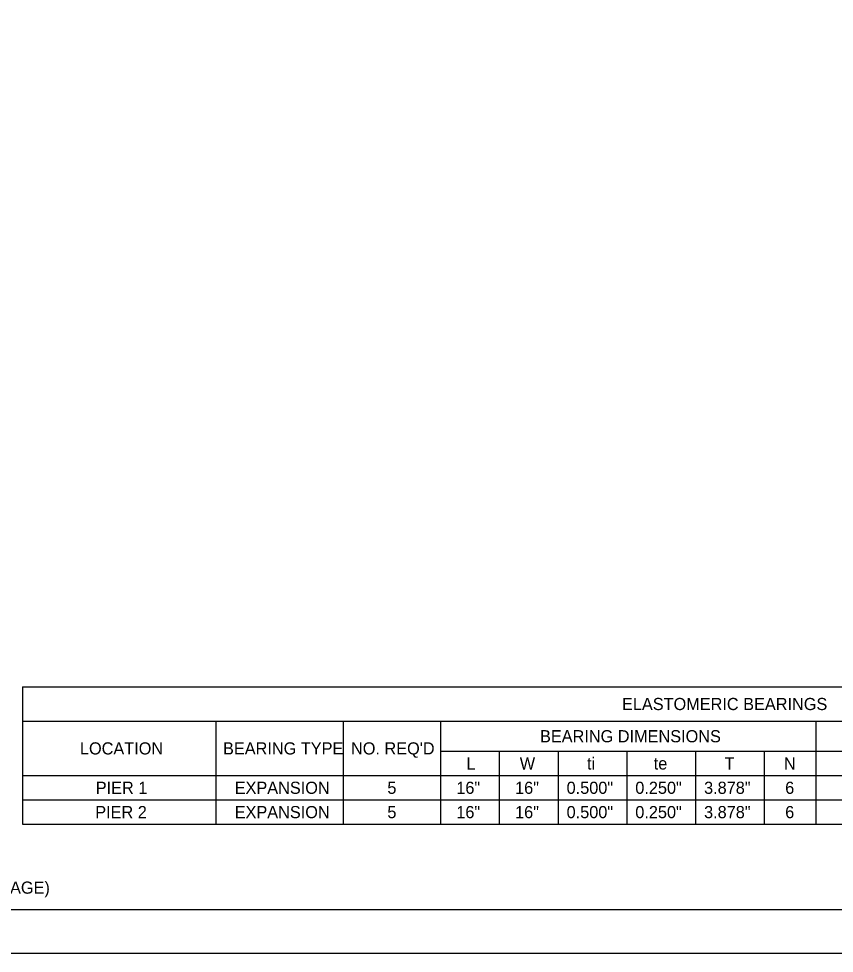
# Model space of a CAD drawing. Extents: x 0 to 34, y 0 to 22.
# Drawn here: x 15.75 to 25.13, y 0 to 10.76 of the extents above; entities that cross this region are included whole.
import ezdxf

# ---------------------------------------------------------------- set-up
doc = ezdxf.new("R2010")
doc.units = 0
for name, color, linetype in [('SH_Border', 7, 'Continuous'), ('SH_Cut_Line', 7, 'Continuous'), ('SH_Text', 7, 'Continuous')]:
    doc.layers.add(name, color=color, linetype=linetype)

msp = doc.modelspace()

# ---------------------------------------------------------------- linework, layer by layer
at = {"layer": 'SH_Border'}
msp.add_lwpolyline([(1.5, 21.5), (33.5, 21.5), (33.5, 0.5), (1.5, 0.5)], close=True, dxfattribs=at)
at = {"layer": 'SH_Cut_Line'}
msp.add_lwpolyline([(0, 0), (34, 0), (34, 22), (0, 22)], close=True, dxfattribs=at)
at = {"layer": 'SH_Text'}
for p, q in [((15.791, 3.066), (31.8, 3.066)), ((15.791, 3.066), (15.791, 1.485)), ((15.791, 2.671), (31.8, 2.671)), ((18.014, 2.671), (18.014, 1.485)), ((19.48, 2.671), (19.48, 1.485)), ((20.6, 2.671), (20.6, 1.485)), ((24.915, 2.671), (24.915, 1.485)), ((20.6, 2.325), (29.972, 2.325)), ((21.275, 2.325), (21.275, 1.485)), ((21.951, 2.325), (21.951, 1.485)), ((22.741, 2.325), (22.741, 1.485)), ((23.532, 2.325), (23.532, 1.485)), ((24.322, 2.325), (24.322, 1.485)), ((15.791, 2.045), (31.8, 2.045)), ((15.791, 1.765), (31.8, 1.765)), ((15.791, 1.485), (31.8, 1.485))]:
    msp.add_line(p, q, dxfattribs=at)

# ---------------------------------------------------------------- texts
for s, p in [('ELASTOMERIC BEARINGS', (22.686, 2.799)), ('BEARING DIMENSIONS', (21.743, 2.428)), ('LOCATION', (16.451, 2.288)), ('BEARING TYPE', (18.097, 2.288)), ("NO. REQ'D", (19.569, 2.288)), ('ti', (22.283, 2.115)), ('L', (20.896, 2.115)), ('W', (21.51, 2.115)), ('te', (23.051, 2.115)), ('T', (23.866, 2.115)), ('N', (24.548, 2.115)), ('PIER 1', (16.633, 1.835)), ('EXPANSION', (18.231, 1.835)), ('5', (19.987, 1.835)), ('16"', (20.78, 1.835)), ('16"', (21.456, 1.835)), ('0.500"', (22.049, 1.835)), ('0.250"', (22.839, 1.835)), ('3.878"', (23.63, 1.835)), ('6', (24.563, 1.835)), ('PIER 2', (16.627, 1.555)), ('EXPANSION', (18.231, 1.555)), ('5', (19.987, 1.555)), ('16"', (20.78, 1.555)), ('16"', (21.456, 1.555)), ('0.500"', (22.049, 1.555)), ('0.250"', (22.839, 1.555)), ('3.878"', (23.63, 1.555)), ('6', (24.563, 1.555)), ('INTERNAL STEEL LAMINATE THICKNESS = 0.1046" (12 GAGE)', (10.592, 0.686))]:
    msp.add_text(s, height=0.14, dxfattribs=at).set_placement(p)

doc.saveas('drawing.dxf')
